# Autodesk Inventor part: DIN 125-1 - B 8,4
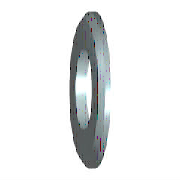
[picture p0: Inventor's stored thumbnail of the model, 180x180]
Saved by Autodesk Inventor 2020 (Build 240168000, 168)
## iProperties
Created: 2008-02
Part Number: DIN 125-1 - B 8,4
Material: Steel, Mild
Document SubType Name: Modeling
Standard: DIN 125-1
Designer: Administrator
Standards Organization: DIN
Language: de-DE
Size Designation: B 8,4
Categories: <MemberInstance><Categories><Category DisplayName="Verbindungselemente" InternalName="e4da775c-781d-43d5-af7c-5136215cf5a6" Mnemonic="FSTN"><Category DisplayNam
Density: 7.86 g/cm^3
Mass: 1.80054 g
Surface Area: 4.0195 cm^2
Volume: 0.229077 cm^3
Appearance: Stahl
IsCustomPart: 0
Author: Administrator
Revision Number: C
Title: Unterlegscheibe
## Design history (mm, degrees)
node "Volumenkörper1"
sketch "Skizze"
  geometry: C1 r 8 at (0, 0); C2 r 4.2 at (0, 0); 1 further point
  constraints: 2 centre point, 2 coincident
  dimensions: "d0" = 8.4 diameter of C2 (= SD1); "d1" = 16 diameter of C1 (= SD2)
extrude "Körper" new body sketch "Skizze" distance "d2" = 1.6 (= SD); taper "d3" = 0 deg
workaxis "Work Axis1"
workplane "Work Plane1"
node "Volumenkörpern"
node "Oberflächenkörpern"
chamfer "Fase" distance "d4" = 0.4 (= PHH); stored, may be unused: angle "d5" = 45 deg, second distance "d8" = 0.4 (= PHH)
other parameters: "SD1" = 8.4 [user parameter; used in 1 equation term], "SD2" = 16 [user parameter; used in 1 equation term], "SD" = 1.6 [user parameter; used in 1 equation term], "PHH" = 0.4 [user parameter; used in 2 equation terms], "FAWI" = 45 deg [user parameter], "d6" = 0, "d7" = 0, "d9" = 0, "d10" = 0, "NND" = 8 [user parameter]
